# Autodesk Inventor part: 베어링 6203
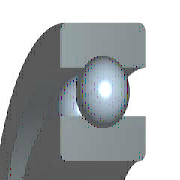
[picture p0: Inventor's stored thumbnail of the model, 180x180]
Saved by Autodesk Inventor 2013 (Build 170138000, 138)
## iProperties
IsCustomPart: 1
Created: 2015-09
Part Number: 베어링 6203
Material: 강철, 연강
Description: 깊은 그루브 볼 베어링
Document SubType Name: Modeling
Standard: KS B 2023
Standards Organization: KS
Language: ko-KR
Size Designation: 6203 - 17 x 40 x 12
Categories: <MemberInstance><Categories><Category DisplayName="샤프트 부품" InternalName="7f7aeb1f-a693-4053-b835-cee3144e0d98" Mnemonic="SHFT"><Category DisplayName="베어링" Inter
Density: 1 g/cm^3
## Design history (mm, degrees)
sketch "스케치" dims "d0" = 5.98 (= -0.26 x WD + 0.26 x BD)
  geometry: L1 (3.01, 14.25)-(8.99, 14.25); L2 (6, 14.25)-(6, 11.26); L3 (6, 14.25)-(6, 17.24); L4 (3.778, 12.249)-(0, 12.249); L5 (0, 8.5)-(12, 8.5); L6 (3.778, 16.251)-(0, 16.251); L7 (0, 20)-(12, 20); L8 (12, 8.5)-(12, 12.249); L9 (8.222, 12.249)-(12, 12.249); L10 (8.222, 16.251)-(12, 16.251); L11 (12, 20)-(12, 16.251); L12 (-1.4, 0)-(8.4, 0) reference; L13 (0, -0.3)-(0, 5.3) reference
  constraints: 22 end point, 4 point on line, 2 collinear, 2 perpendicular, 2 symmetric about line, 1 midpoint, 1 parallel, 14 other
  dimensions: "d9" = 17 diameter of L5 L12 (= WD); "d11" = 40 diameter of L7 L12 (= BD); "d12" = 12 distance between parallel lines of L8 L13 (= KB); "d13" = 24.498 diameter of L9 L12 (= 0.326 x BD + 0.674 x WD)
revolve "본체" stored, may be unused: angle "d6" = 90 deg
revolve "볼" stored, may be unused: angle "d7" = 90 deg
pattern_circular "IDS_ARRAYBALL[SIMPL:T]" dims angle "d3" = 360 deg
body "Solid1"
fillet "모깎기1" dims "d1" = 0.6 (= KRS)
other parameters: "WD" = 17 [user parameter; used in 5 equation terms], "BD" = 40 [user parameter; used in 5 equation terms], "KB" = 12 [user parameter; used in 1 equation term], "KRS" = 0.6 [user parameter; used in 1 equation term], "d4" = 0, "d5" = 0, "d8" = 0, "d14" = 0, "d15" = 0, "BBA" = 0 [user parameter], "BC0" = 4750000 [user parameter], "BC" = 9560000 [user parameter], "WR" = 8.5 (= 0.5 x WD) [user parameter]
